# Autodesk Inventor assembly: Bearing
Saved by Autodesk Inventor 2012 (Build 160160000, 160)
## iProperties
Created: 2011-12
Part Number: Bearing
Document SubType Name: Assembly
Designer: Admin
ClientObjectVersion: 1
Author: Admin
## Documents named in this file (2)
- C:\Documents and Settings\All Users\Autodesk Learning\Inventor 2009\Advanced Assembly and Machine Design\Workspace\GearBox-A\Design Accelerator\Bearing1.iam
- C:\Documents and Settings\All Users\Autodesk Learning\Inventor 2009\Advanced Assembly and Machine Design\Libraries\Content Center Files\en-US\DIN BEARING(1)\DIN 625 SKF - SKF 6304.ipt
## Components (1 placed, 1 different names)
1. DIN 625 SKF 6304:1
